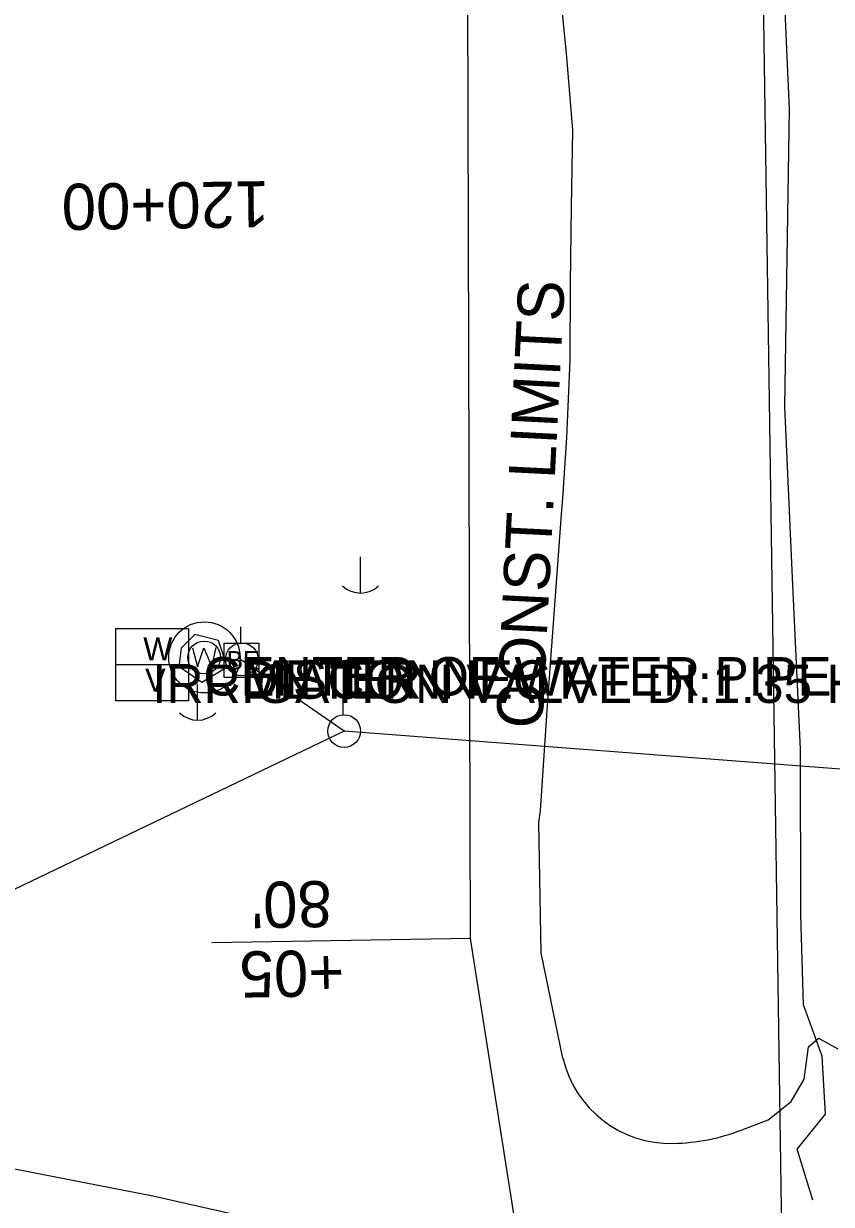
# Model space of a CAD drawing. Extents: x 1674300 to 1677920, y 225056 to 231852.
# Drawn here: x 1677236.4 to 1677341.5, y 229147 to 229300.7 of the extents above; entities that cross this region are included whole.
import ezdxf

# ---------------------------------------------------------------- set-up
doc = ezdxf.new("R2010")
doc.units = 0
for name, color, linetype in [('R_Annotation', 7, 'Continuous'), ('R_Horz Alg Annot', 7, 'Continuous'), ('R_Proposed Const Limits_Cut', 7, 'Continuous'), ('R_ROW', 7, 'Continuous'), ('R_ROW Annot', 7, 'Continuous'), ('S_DITCHLINE', 7, 'Continuous'), ('S_EDGE_CONCRETE', 7, 'Continuous'), ('S_ELECTRIC_UTILITIES', 7, 'Continuous'), ('S_ELECTRIC_UTILITIES_ANNOT', 7, 'Continuous'), ('S_EXIST_ROW', 7, 'Continuous'), ('S_STREAM', 7, 'Continuous'), ('S_UTILITY_POLE', 7, 'Continuous'), ('S_UTL_PT_SYM', 7, 'Continuous'), ('S_WATER_UTILITIES', 7, 'Continuous'), ('S_WATER_UTILITIES_ANNOT', 7, 'Continuous'), ('S_WATER_WELL_ANNOT', 7, 'Continuous')]:
    doc.layers.add(name, color=color, linetype=linetype)

msp = doc.modelspace()

# ---------------------------------------------------------------- linework, layer by layer
at = {"layer": 'R_Proposed Const Limits_Cut'}
for points in [[(1677306.57, 229166.08), (1677303.76, 229179.76), (1677303.46, 229196.75), (1677303.68, 229198.31), (1677304.24, 229206.76), (1677304.54, 229211.31), (1677304.92, 229216.77), (1677305.65, 229226.79), (1677306.39, 229236.8), (1677306.56, 229238.95), (1677307.11, 229246.81), (1677307.54, 229256.82), (1677307.57, 229266.82), (1677307.7, 229276.82), (1677307.87, 229286.82), (1677307.05, 229296.81), (1677306.05, 229306.8)], [(1677329.78, 229156.7), (1677333.28, 229158.03), (1677336.27, 229160.42), (1677337.95, 229163.34), (1677338.51, 229167.53)], [(1677338.51, 229167.53), (1677339.81, 229168.69), (1677342.35, 229167.27)]]:
    msp.add_lwpolyline(points, dxfattribs=at)
for centre, radius, start, end in [((1677320.6, 229169.36), 14.4, 192.9886, 271.4218), ((1677320.29, 229181.67), 26.71, 271.4218, 290.8163)]:
    msp.add_arc(centre, radius, start, end, dxfattribs=at)
at = {"layer": 'R_ROW'}
msp.add_line((1677294.58, 229181.63), (1677293.32, 229626.65), dxfattribs=at)
msp.add_lwpolyline([(1677280.82, 228594.47), (1677312.38, 228785.76), (1677312.38, 228785.76), (1677316.54, 229041.92), (1677294.58, 229181.63), (1677294.58, 229181.63)], dxfattribs=at)
at = {"layer": 'R_ROW Annot'}
msp.add_line((1677294.58, 229181.63), (1677260.94, 229181.07), dxfattribs=at)
at = {"layer": 'S_DITCHLINE'}
msp.add_lwpolyline([(1677339.09, 229147.6), (1677337.05, 229154.23), (1677340.76, 229158.8), (1677340.29, 229166.32), (1677337.9, 229173.01), (1677337.54, 229184.7), (1677337.47, 229206.29), (1677336.46, 229228.55), (1677335.46, 229250.81), (1677335.75, 229270.19), (1677336.05, 229289.58), (1677334.99, 229313.98), (1677333.93, 229338.37), (1677333.99, 229360.23), (1677334.04, 229382.08), (1677334.5, 229402.19), (1677334.96, 229422.29), (1677334.69, 229446.15), (1677334.41, 229470.02), (1677334.41, 229473.73)], dxfattribs=at)
at = {"layer": 'S_EDGE_CONCRETE'}
msp.add_lwpolyline([(1677256.8, 229216.96), (1677259.63, 229214.99), (1677262.93, 229217), (1677261.81, 229220.41), (1677258.73, 229221.18), (1677256.93, 229219.41), (1677256.67, 229217.35)], close=True, dxfattribs=at)
at = {"layer": 'S_ELECTRIC_UTILITIES'}
for p, q in [((1677278.13, 229208.63), (1677264.79, 229217.83)), ((1677278.13, 229208.63), (1677031.23, 229090)), ((1677541.68, 229188.35), (1677278.13, 229208.63))]:
    msp.add_line(p, q, dxfattribs=at)
for points in [[(1677262.52, 229215.58), (1677262.52, 229220.08), (1677267.02, 229220.08), (1677267.02, 229215.58)], [(1677262.53, 229215.58), (1677262.53, 229220.08), (1677267.03, 229220.08), (1677267.03, 229215.58)]]:
    msp.add_lwpolyline(points, close=True, dxfattribs=at)
at = {"layer": 'S_EXIST_ROW'}
msp.add_line((1677337.07, 229010.49), (1677299.88, 231497.46), dxfattribs=at)
at = {"layer": 'S_STREAM'}
msp.add_lwpolyline([(1677274.96, 229143.23), (1677253.24, 229148.13), (1677240.58, 229150.59), (1677227.91, 229153.05), (1677211.81, 229151.5), (1677195.72, 229149.95), (1677183.04, 229148.43), (1677170.36, 229146.92)], dxfattribs=at)
at = {"layer": 'S_UTILITY_POLE'}
for p, q in [((1677280.21, 229231.29), (1677280.21, 229226.56)), ((1677264.7, 229220.1), (1677264.7, 229222.21)), ((1677259.03, 229214.76), (1677259.03, 229210.03)), ((1677278.01, 229210.77), (1677278.01, 229212.88))]:
    msp.add_line(p, q, dxfattribs=at)
for centre in [(1677264.82, 229217.96), (1677278.13, 229208.63)]:
    msp.add_circle(centre, 2.13, dxfattribs=at)
for centre in [(1677280.27, 229229.99), (1677259.09, 229213.46)]:
    msp.add_arc(centre, 3.41, 226.3972, 313.6028, dxfattribs=at)
at = {"layer": 'S_UTL_PT_SYM'}
for points in [[(1677264.79, 229217.83), (1677264.79, 229217.88), (1677264.79, 229217.83), (1677264.74, 229217.83), (1677264.79, 229217.83), (1677264.79, 229217.78), (1677264.79, 229217.83), (1677264.84, 229217.83)], [(1677278.13, 229208.63), (1677278.13, 229208.68), (1677278.13, 229208.63), (1677278.08, 229208.63), (1677278.13, 229208.63), (1677278.13, 229208.58), (1677278.13, 229208.63), (1677278.18, 229208.63)], [(1677278.13, 229208.63), (1677278.13, 229208.68), (1677278.13, 229208.63), (1677278.08, 229208.63), (1677278.13, 229208.63), (1677278.13, 229208.58), (1677278.13, 229208.63), (1677278.18, 229208.63)]]:
    msp.add_lwpolyline(points, dxfattribs=at)
at = {"layer": 'S_WATER_UTILITIES'}
for p, q in [((1677248.46, 229221.97), (1677257.88, 229221.97)), ((1677248.46, 229212.56), (1677248.46, 229221.97)), ((1677257.88, 229221.97), (1677257.88, 229212.56)), ((1677258.4, 229219.47), (1677259.06, 229216.99)), ((1677259.06, 229216.99), (1677259.87, 229219.47)), ((1677259.87, 229219.47), (1677260.92, 229216.99)), ((1677260.92, 229216.99), (1677261.5, 229219.51)), ((1677248.46, 229217.28), (1677257.88, 229217.28)), ((1677257.88, 229212.56), (1677248.46, 229212.56))]:
    msp.add_line(p, q, dxfattribs=at)
for centre, radius in [((1677259.96, 229218.21), 4.63), ((1677259.93, 229218.21), 2.13)]:
    msp.add_circle(centre, radius, dxfattribs=at)

# ---------------------------------------------------------------- texts
at = {"layer": 'R_Annotation'}
msp.add_text('CONST. LIMITS', height=6, rotation=87.1086, dxfattribs=at).set_placement((1677303.88, 229208.85))
at = {"layer": 'R_Horz Alg Annot'}
msp.add_text('120+00', height=6, rotation=180.8056, dxfattribs=at).set_placement((1677268.35, 229280.19))
at = {"layer": 'R_ROW Annot'}
for s, p in [("80'", (1677276.47, 229189.14)), ('+05', (1677278.09, 229180.16))]:
    msp.add_text(s, height=6, rotation=180.9497, dxfattribs=at).set_placement(p)
at = {"layer": 'S_ELECTRIC_UTILITIES'}
for p in [(1677262.84, 229216.63), (1677262.85, 229216.63)]:
    msp.add_text('BE', height=2.4, rotation=360, dxfattribs=at).set_placement(p)
at = {"layer": 'S_ELECTRIC_UTILITIES_ANNOT'}
for s, p in [('DISCONNECT', (1677264.79, 229212.83)), ('METER', (1677264.8, 229212.83))]:
    msp.add_text(s, height=5, dxfattribs=at).set_placement(p)
at = {"layer": 'S_WATER_UTILITIES'}
for s, p in [('W', (1677252.01, 229217.81)), ('V', (1677252.25, 229213.75))]:
    msp.add_text(s, height=3, rotation=360, dxfattribs=at).set_placement(p)
at = {"layer": 'S_WATER_UTILITIES_ANNOT'}
msp.add_text('IRRIGATION VALVE DI:1.35 HT:5.00', height=5, dxfattribs=at).set_placement((1677253.17, 229212.28))
at = {"layer": 'S_WATER_WELL_ANNOT'}
msp.add_text('CENTER OF WATER PIPE', height=5, dxfattribs=at).set_placement((1677259.81, 229213.25))

doc.saveas('drawing.dxf')
